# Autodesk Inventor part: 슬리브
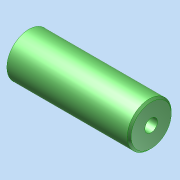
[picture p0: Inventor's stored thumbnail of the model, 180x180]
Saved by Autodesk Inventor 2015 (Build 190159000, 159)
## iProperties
Created: 2026-09
Part Number: 슬리브
Material: 일반
Document SubType Name: Modeling
Designer: SCD-A06
Density: 1 g/cm^3
Appearance: 기본값
Author: SCD-A06
Author: jhkim
Creation Date: 2026-08-27
Sending System: Autodesk Inventor 2027
Preprocessor: ST-DEVELOPER v20.1
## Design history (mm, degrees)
node "슬리브1"
node "솔리드1"
node "기준1"
